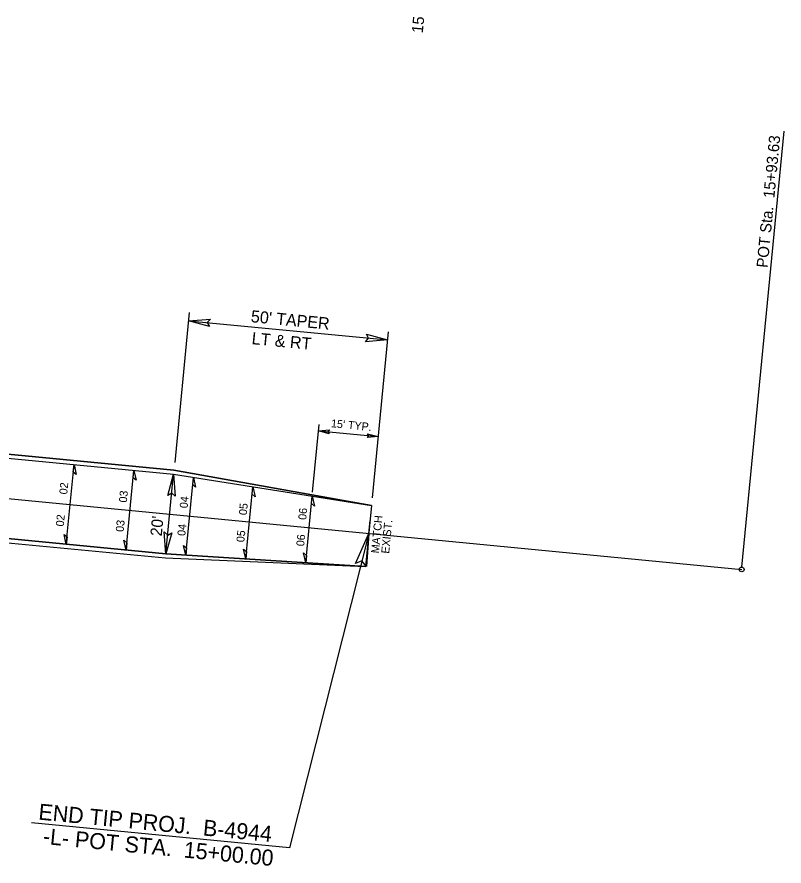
# Model space of a CAD drawing. Extents: x 2061030 to 2061632, y 912568 to 912882.
# Drawn here: x 2061440.1 to 2061631.8, y 912592.2 to 912804.3 of the extents above; entities that cross this region are included whole.
import ezdxf

# ---------------------------------------------------------------- set-up
doc = ezdxf.new("R2010")
doc.units = 0
for name, color, linetype in [('Prop Dimension', 7, 'Continuous'), ('Prop Dimension Text', 7, 'Continuous'), ('Prop EOT', 7, 'Continuous'), ('Prop Horizontal Alignment', 7, 'Continuous'), ('Prop Horizontal Alignment Station Label', 7, 'Continuous'), ('Prop Horizontal Alignment Tick Label', 7, 'Continuous'), ('Prop Horizontal Alignment Tick Large', 7, 'Continuous'), ('Prop Paved Shoulder', 7, 'Continuous'), ('Prop Shade Medium', 7, 'Continuous'), ('Prop Superelevation  Arrow CELL', 7, 'Continuous'), ('Prop Superelevation Label', 7, 'Continuous'), ('Prop Terminator CELL', 7, 'Continuous')]:
    doc.layers.add(name, color=color, linetype=linetype)

msp = doc.modelspace()

# ---------------------------------------------------------------- linework, layer by layer
at = {"layer": 'Prop Dimension'}
for p, q in [((2061483.11, 912730.51), (2061479.49, 912692.99)), ((2061482.91, 912728.44), (2061532.68, 912723.63)), ((2061532.88, 912725.7), (2061528.87, 912684.17)), ((2061477.28, 912670.17), (2061479.21, 912690.07)), ((2061528.01, 912675.31), (2061508.21, 912596.76)), ((2061508.21, 912596.76), (2061443.68, 912603))]:
    msp.add_line(p, q, dxfattribs=at)
at = {"layer": 'Prop EOT'}
for p, q in [((2061104.02, 912706.25), (2061477.28, 912670.17)), ((2061429.44, 912694.88), (2061479.21, 912690.07)), ((2061479.21, 912690.07), (2061528.68, 912682.25)), ((2061528.68, 912682.25), (2061527.21, 912667.04)), ((2061477.28, 912670.17), (2061527.21, 912667.04))]:
    msp.add_line(p, q, dxfattribs=at)
at = {"layer": 'Prop Horizontal Alignment'}
msp.add_line((2061030.33, 912723.42), (2061621.2, 912666.3), dxfattribs=at)
at = {"layer": 'Prop Horizontal Alignment Station Label'}
msp.add_line((2061621.26, 912666.9), (2061631.79, 912775.79), dxfattribs=at)
msp.add_circle((2061621.2, 912666.3), 0.6, dxfattribs=at)
at = {"layer": 'Prop Horizontal Alignment Tick Large'}
msp.add_line((2061528.01, 912675.31), (2061528.32, 912678.49), dxfattribs=at)
at = {"layer": 'Prop Paved Shoulder'}
for p, q in [((2061387.27, 912699.96), (2061479.3, 912691.07)), ((2061479.3, 912691.07), (2061528.68, 912682.25)), ((2061385.15, 912678.07), (2061477.19, 912669.17)), ((2061477.19, 912669.17), (2061527.21, 912667.04))]:
    msp.add_line(p, q, dxfattribs=at)
at = {"layer": 'Prop Shade Medium'}
for p, q in [((2061479.3, 912691.07), (2061387.27, 912699.96)), ((2061429.44, 912694.88), (2061479.21, 912690.07)), ((2061528.68, 912682.25), (2061479.3, 912691.07)), ((2061479.21, 912690.07), (2061528.68, 912682.25)), ((2061477.28, 912670.17), (2061321.14, 912685.26)), ((2061385.15, 912678.07), (2061477.19, 912669.17)), ((2061477.19, 912669.17), (2061527.21, 912667.04)), ((2061527.21, 912667.04), (2061477.28, 912670.17))]:
    msp.add_line(p, q, dxfattribs=at)
at = {"layer": 'Prop Superelevation  Arrow CELL'}
for p, q in [((2061452.4, 912672.57), (2061454.32, 912692.48)), ((2061467.33, 912671.13), (2061469.25, 912691.04)), ((2061482.27, 912669.85), (2061484.15, 912689.29)), ((2061497.25, 912668.92), (2061499, 912686.95)), ((2061512.23, 912667.98), (2061513.84, 912684.6))]:
    msp.add_line(p, q, dxfattribs=at)
for points in [[(2061454.32, 912692.48), (2061454.89, 912690.01), (2061454.14, 912690.64)], [(2061469.25, 912691.04), (2061469.82, 912688.57), (2061469.07, 912689.19)], [(2061484.15, 912689.29), (2061484.72, 912686.83), (2061483.98, 912687.45)], [(2061499, 912686.95), (2061499.56, 912684.48), (2061498.82, 912685.1)], [(2061513.84, 912684.6), (2061514.41, 912682.13), (2061513.66, 912682.76)], [(2061452.4, 912672.57), (2061451.83, 912675.04), (2061452.58, 912674.41)], [(2061467.33, 912671.13), (2061466.76, 912673.59), (2061467.51, 912672.97)], [(2061482.27, 912669.85), (2061481.71, 912672.32), (2061482.45, 912671.69)], [(2061497.25, 912668.92), (2061496.69, 912671.38), (2061497.43, 912670.76)], [(2061512.23, 912667.98), (2061511.67, 912670.44), (2061512.41, 912669.82)]]:
    msp.add_lwpolyline(points, close=True, dxfattribs=at)
at = {"layer": 'Prop Superelevation Label'}
for p, q in [((2061513.94, 912685.61), (2061515.57, 912702.48)), ((2061515.42, 912700.92), (2061530.35, 912699.48))]:
    msp.add_line(p, q, dxfattribs=at)
at = {"layer": 'Prop Terminator CELL'}
for points in [[(2061488.2, 912726.99), (2061482.91, 912728.44), (2061488.41, 912728.87), (2061487.63, 912727.98)], [(2061527.4, 912725.07), (2061532.68, 912723.63), (2061527.19, 912723.2), (2061527.96, 912724.08)], [(2061518.06, 912700.2), (2061515.42, 912700.92), (2061518.17, 912701.14), (2061517.78, 912700.7)], [(2061527.71, 912700.2), (2061530.35, 912699.48), (2061527.6, 912699.27), (2061527.99, 912699.71)], [(2061477.76, 912684.79), (2061479.21, 912690.07), (2061479.64, 912684.58), (2061478.75, 912685.36)], [(2061478.73, 912675.45), (2061477.28, 912670.17), (2061476.85, 912675.66), (2061477.74, 912674.88)], [(2061524.68, 912667.8), (2061528.01, 912675.31), (2061527.42, 912667.06), (2061526.27, 912668.41)]]:
    msp.add_lwpolyline(points, close=True, dxfattribs=at)

# ---------------------------------------------------------------- texts
at = {"layer": 'Prop Dimension Text'}
for s, height, rotation, p in [("50' TAPER", 3, 354.4787, (2061498.43, 912728.1)), ('LT & RT', 3, 354.4787, (2061498.63, 912722.6)), ("20'", 2.88, 84.4787, (2061476.24, 912674.5)), ('MATCH', 2, 84.4787, (2061530.54, 912670.25)), ('EXIST.', 2, 84.4787, (2061533.08, 912670.18)), ('END TIP PROJ.  B-4944', 4, 354.4787, (2061445.31, 912603.82)), ('-L- POT STA.  15+00.00', 4, 354.4787, (2061446.42, 912597.74))]:
    msp.add_text(s, height=height, rotation=rotation, dxfattribs=at).set_placement(p)
at = {"layer": 'Prop Horizontal Alignment Station Label'}
msp.add_text('POT Sta.  15+93.63', height=2.8, rotation=84.4787, dxfattribs=at).set_placement((2061627.68, 912741.57))
at = {"layer": 'Prop Horizontal Alignment Tick Label'}
msp.add_text('15', height=2.8, rotation=84.4787, dxfattribs=at).set_placement((2061541.49, 912800.21))
at = {"layer": 'Prop Superelevation Label'}
for s, rotation, p in [("15' TYP.", 354.4787, (2061518.49, 912701.85)), ('02', 84.4787, (2061452.61, 912684.98)), ('03', 84.4787, (2061467.52, 912682.94)), ('04', 84.4787, (2061482.7, 912681.53)), ('05', 84.4787, (2061497.49, 912679.8)), ('02', 84.4787, (2061451.75, 912676.97)), ('06', 84.4787, (2061512.34, 912678.62)), ('03', 84.4787, (2061466.71, 912675.61)), ('04', 84.4787, (2061482.12, 912674.6)), ('05', 84.4787, (2061496.88, 912673.03)), ('06', 84.4787, (2061511.84, 912672.02))]:
    msp.add_text(s, height=2, rotation=rotation, dxfattribs=at).set_placement(p)

doc.saveas('drawing.dxf')
